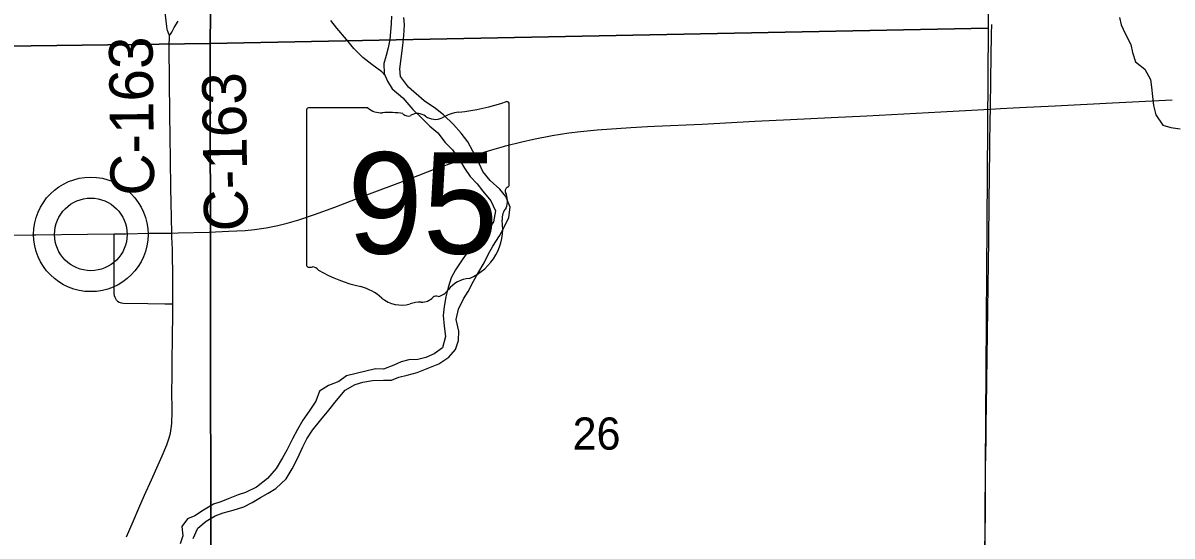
# Model space of a CAD drawing. Extents: x 0 to 45.9, y 0 to 22.
# Drawn here: x 3.224 to 4.718, y 15.053 to 15.719 of the extents above; entities that cross this region are included whole.
import ezdxf

# ---------------------------------------------------------------- set-up
doc = ezdxf.new("R2010")
doc.units = 0
for name, color, linetype in [('GM_X_County_Road', 7, 'Continuous'), ('GM_X_County_Road_Text', 7, 'Continuous'), ('GM_X_Major_River', 7, 'Continuous'), ('GM_X_Minor_River', 7, 'Continuous'), ('GM_X_Section', 7, 'Continuous'), ('GM_X_Section_Text', 7, 'Continuous'), ('GM_X_State_Location', 7, 'Continuous'), ('GM_X_State_Route', 7, 'Continuous'), ('GM_X_State_Shield', 7, 'Continuous'), ('GM_X_Township_Road', 7, 'Continuous'), ('GM_X_Unincorporated', 7, 'Continuous'), ('GM_X_Unincorporated_Location', 7, 'Continuous')]:
    doc.layers.add(name, color=color, linetype=linetype)

msp = doc.modelspace()

# ---------------------------------------------------------------- linework, layer by layer
at = {"layer": 'GM_X_County_Road'}
for points in [[(3.4142, 15.703), (3.4133, 15.7048), (3.4123, 15.7073), (3.4116, 15.7095), (3.4113, 15.7115), (3.4107, 15.7149), (3.4041, 15.7704)], [(3.4171, 15.4464), (3.4162, 15.4859), (3.4161, 15.5045), (3.4157, 15.5418), (3.4148, 15.6008), (3.4139, 15.6878), (3.4142, 15.703)], [(4.475, 15.0359), (4.4752, 15.1016), (4.4753, 15.1451), (4.4755, 15.1544), (4.476, 15.1832), (4.4763, 15.2003), (4.4767, 15.2194), (4.4772, 15.2538), (4.4785, 15.347), (4.4794, 15.4372), (4.48, 15.4869), (4.481, 15.5553), (4.4815, 15.5988), (4.4816, 15.6019), (4.4817, 15.6073)], [(3.4186, 15.3543), (3.4186, 15.3633), (3.4184, 15.3851), (3.418, 15.4255), (3.4173, 15.441), (3.4171, 15.4464)], [(3.3585, 15.0517), (3.367, 15.0716), (3.3743, 15.0887), (3.3818, 15.1058), (3.3907, 15.1256), (3.4047, 15.1568), (3.4106, 15.1712), (3.4138, 15.1801), (3.4155, 15.1861), (3.4166, 15.1923), (3.4172, 15.1986), (3.4177, 15.2142), (3.4174, 15.2422), (3.4177, 15.2577), (3.4177, 15.2701), (3.4178, 15.2856), (3.4182, 15.3043), (3.4181, 15.3167), (3.4187, 15.3353), (3.4187, 15.3478), (3.4186, 15.3543)]]:
    msp.add_lwpolyline(points, dxfattribs=at)
at = {"layer": 'GM_X_Major_River'}
for points in [[(3.4448, 15.0494), (3.451, 15.0626), (3.4618, 15.0719), (3.4736, 15.079), (3.4839, 15.0826), (3.4972, 15.0862), (3.511, 15.0906), (3.5217, 15.0962), (3.5327, 15.1025), (3.5427, 15.1084), (3.5526, 15.1143), (3.5661, 15.127), (3.5739, 15.1398), (3.5805, 15.1534), (3.5875, 15.1685), (3.5926, 15.179), (3.6003, 15.1903), (3.6108, 15.2035), (3.6216, 15.2162), (3.6312, 15.2286), (3.6428, 15.2421), (3.6558, 15.2495), (3.6657, 15.2524), (3.6782, 15.2549), (3.6927, 15.2551), (3.7029, 15.2553), (3.7124, 15.259), (3.7231, 15.2615), (3.7364, 15.2651), (3.7494, 15.2703), (3.7643, 15.2765), (3.7773, 15.2851), (3.7862, 15.2952), (3.7901, 15.3065), (3.7903, 15.3187), (3.7871, 15.3339), (3.7899, 15.3475), (3.7965, 15.3607), (3.8024, 15.3705), (3.8094, 15.3836), (3.8152, 15.3938), (3.8234, 15.4077), (3.8288, 15.4183), (3.8346, 15.4292), (3.8432, 15.4428), (3.849, 15.4529), (3.8553, 15.4665), (3.857, 15.4801), (3.8515, 15.4939), (3.8436, 15.5034), (3.8313, 15.5146), (3.8215, 15.5265), (3.8153, 15.5406), (3.802, 15.5647), (3.7934, 15.5762), (3.7837, 15.5873), (3.7706, 15.6), (3.7601, 15.6081), (3.7454, 15.6182), (3.7251, 15.6359), (3.7147, 15.6497), (3.7137, 15.6596), (3.7154, 15.6732), (3.7175, 15.6899), (3.7188, 15.7032), (3.7198, 15.7168), (3.7188, 15.7263)], [(3.7029, 15.7284), (3.7024, 15.7189), (3.7018, 15.7079), (3.7006, 15.6977), (3.6985, 15.6871), (3.6961, 15.6769), (3.6929, 15.6667), (3.6935, 15.6538), (3.6975, 15.6439), (3.7039, 15.6336), (3.7177, 15.622), (3.7308, 15.607), (3.7409, 15.597), (3.7529, 15.5851), (3.763, 15.5766), (3.7727, 15.564), (3.7821, 15.5544), (3.7921, 15.5402), (3.7977, 15.5306), (3.8051, 15.5199), (3.8141, 15.5103), (3.8216, 15.5007), (3.832, 15.4881), (3.8383, 15.4754), (3.8355, 15.4607), (3.8273, 15.4483), (3.815, 15.4374), (3.8054, 15.4266), (3.7957, 15.413), (3.786, 15.3984), (3.7806, 15.3882), (3.7766, 15.3757), (3.7734, 15.3633), (3.7714, 15.3508), (3.7701, 15.339), (3.7714, 15.3254), (3.7731, 15.3117), (3.7691, 15.2973), (3.7584, 15.2895), (3.7477, 15.2847), (3.737, 15.2822), (3.7253, 15.2816), (3.7154, 15.2791), (3.7058, 15.2746), (3.6925, 15.2695), (3.6819, 15.27), (3.6445, 15.2607)], [(3.6445, 15.2607), (3.6346, 15.2532), (3.6209, 15.2481), (3.6094, 15.2407), (3.6043, 15.2278), (3.5957, 15.2147), (3.5876, 15.203), (3.5806, 15.191), (3.574, 15.1789), (3.567, 15.1642), (3.5611, 15.1541), (3.553, 15.1405), (3.5418, 15.1274), (3.5272, 15.1162), (3.5131, 15.1092), (3.5036, 15.1063), (3.4906, 15.1011), (3.4811, 15.0971), (3.4715, 15.0938), (3.4585, 15.086), (3.4471, 15.079), (3.4375, 15.0749), (3.4302, 15.0648), (3.4315, 15.0526), (3.428, 15.0424)]]:
    msp.add_lwpolyline(points, dxfattribs=at)
at = {"layer": 'GM_X_Minor_River'}
for points in [[(3.6945, 15.6513), (3.6905, 15.6557), (3.6774, 15.6654), (3.6657, 15.6743), (3.6537, 15.6862), (3.6444, 15.6981), (3.6317, 15.7127), (3.6242, 15.7227)], [(4.6495, 15.7263), (4.6517, 15.7168), (4.6568, 15.7057), (4.6642, 15.6912), (4.6664, 15.6809), (4.6704, 15.6687), (4.6824, 15.6595), (4.6898, 15.6457), (4.6912, 15.6358), (4.6925, 15.6237), (4.6939, 15.6123), (4.6968, 15.6001), (4.7057, 15.5867), (4.7163, 15.5835), (4.7284, 15.5818)]]:
    msp.add_lwpolyline(points, dxfattribs=at)
at = {"layer": 'GM_X_Section'}
for points in [[(3.479, 16.7029), (4.4801, 16.7228), (4.4787, 15.7127), (3.467, 15.6926)], [(3.479, 16.7029), (3.467, 15.6926), (2.4689, 15.6797), (2.4763, 16.6833)], [(4.4787, 15.7127), (4.4719, 14.697), (3.9797, 14.6959), (3.4686, 14.6772), (3.467, 15.6926)], [(3.467, 15.6926), (3.4686, 14.6772), (2.4618, 14.6575), (2.4689, 15.6797)]]:
    msp.add_lwpolyline(points, close=True, dxfattribs=at)
at = {"layer": 'GM_X_State_Route'}
for points in [[(4.0359, 15.5847), (4.0449, 15.5852), (4.107, 15.588), (4.1752, 15.5916), (4.2217, 15.5939), (4.2745, 15.5965), (4.321, 15.5989), (4.4171, 15.6041), (4.473, 15.6068), (4.4817, 15.6073), (4.4946, 15.6081), (4.5195, 15.6095), (4.566, 15.6116), (4.6404, 15.6157), (4.718, 15.6193)], [(3.8484, 15.5588), (3.8512, 15.5596), (3.8723, 15.5649), (3.8875, 15.5684), (3.9119, 15.573), (3.9334, 15.5765), (3.9488, 15.5785), (3.9705, 15.5805), (4.0139, 15.5836), (4.0359, 15.5847)], [(3.4171, 15.4464), (3.4257, 15.4465), (3.466, 15.4476), (3.4908, 15.4486), (3.5125, 15.4498), (3.5248, 15.4511), (3.5401, 15.4533), (3.5553, 15.4563), (3.5673, 15.4592), (3.5822, 15.4636), (3.6028, 15.4705), (3.629, 15.48), (3.6639, 15.4932), (3.7278, 15.5173), (3.7597, 15.5296), (3.8095, 15.5472), (3.8302, 15.5538), (3.8484, 15.5588)], [(2.1, 15.4054), (2.1219, 15.4061), (2.1715, 15.4081), (2.214, 15.4101), (2.218, 15.4102), (2.2708, 15.4121), (2.3732, 15.4164), (2.435, 15.419), (2.5044, 15.4217), (2.5827, 15.4248), (2.6511, 15.4278), (2.7096, 15.4297), (2.7146, 15.4298), (2.8637, 15.4346), (2.9102, 15.4358), (2.9816, 15.4382), (3.0499, 15.4401), (3.1307, 15.4419), (3.1835, 15.4434), (3.2362, 15.4441), (3.2403, 15.4442)], [(3.2403, 15.4442), (3.3077, 15.4451), (3.3424, 15.4454), (3.3573, 15.4455), (3.3884, 15.4461), (3.4171, 15.4464)]]:
    msp.add_lwpolyline(points, dxfattribs=at)
at = {"layer": 'GM_X_State_Shield'}
for p, q in [((3.8559, 15.5092), (3.8559, 15.6139)), ((3.5922, 15.6055), (3.5922, 15.4054)), ((3.672, 15.6089), (3.5948, 15.6089)), ((3.8558, 15.5092), (3.8559, 15.5092))]:
    msp.add_line(p, q, dxfattribs=at)
for centre, radius, start, end in [((3.7619, 15.8817), 0.2796, 275.8445, 288.9065), ((3.8529, 15.6143), 0.00294, 351.8621, 97.738), ((3.5952, 15.6059), 0.00305, 98.1301, 188.1301), ((3.6904, 15.6321), 0.0296, 231.6195, 271.1119), ((3.7002, 15.4966), 0.1064, 80.4867, 94.9883), ((3.7244, 15.6069), 0.00855, 219.7921, 297.1024), ((3.7369, 15.5838), 0.0178, 54.4667, 119.1411), ((3.7599, 15.6155), 0.0214, 233.8562, 294.8282), ((3.7976, 15.5478), 0.0563, 97.3462, 120.7689), ((3.8527, 15.5088), 0.00314, 289.6038, 7.7341), ((3.8552, 15.5015), 0.00454, 107.944, 210.337), ((3.8263, 15.4883), 0.0273, 340.033, 23.6496), ((3.8664, 15.4654), 0.0198, 136.8065, 186.9296), ((3.7776, 15.4521), 0.0699, 292.3089, 8.9858), ((3.5953, 15.4049), 0.00308, 171.9584, 258.3066), ((3.5957, 15.4254), 0.0235, 267.339, 280.6039), ((3.6005, 15.3938), 0.00848, 29.7484, 93.2717), ((3.7076, 15.5736), 0.2019, 240.4129, 257.1985), ((3.6474, 15.3154), 0.0632, 47.1842, 75.836), ((3.8071, 15.3492), 0.0383, 94.4031, 142.5768), ((3.7157, 15.3928), 0.0401, 230.7004, 286.2918), ((3.7418, 15.3778), 0.0214, 268.777, 315.5493), ((3.7611, 15.3584), 0.00601, 65.7517, 132.6484), ((3.7586, 15.386), 0.0226, 282.8732, 323.2771), ((3.7389, 15.3236), 0.0329, 85.6951, 111.2099)]:
    msp.add_arc(centre, radius, start, end, dxfattribs=at)
at = {"layer": 'GM_X_Township_Road'}
for points in [[(3.4142, 15.703), (3.4155, 15.7047), (3.4172, 15.7074), (3.4204, 15.7133), (3.4256, 15.7219)], [(4.4817, 15.6073), (4.4824, 15.647), (4.4825, 15.6746), (4.483, 15.7052), (4.4834, 15.7174)], [(3.3452, 15.3593), (3.3443, 15.3609), (3.3435, 15.3626), (3.3428, 15.3646), (3.3423, 15.3677), (3.3421, 15.3709), (3.3423, 15.3835), (3.3423, 15.3962), (3.3423, 15.4183), (3.3422, 15.4342), (3.3423, 15.4405), (3.3424, 15.4454)], [(3.3452, 15.3593), (3.3466, 15.3579), (3.3487, 15.3566), (3.3514, 15.3556), (3.3545, 15.3551), (3.386, 15.3547), (3.4082, 15.3545), (3.4113, 15.3545), (3.4186, 15.3543)]]:
    msp.add_lwpolyline(points, dxfattribs=at)
at = {"layer": 'GM_X_Unincorporated'}
for radius in [0.0744, 0.0472]:
    msp.add_circle((3.3119, 15.4446), radius, dxfattribs=at)
at = {"layer": 'GM_X_Unincorporated_Location'}
msp.add_line((3.3119, 15.4446), (3.3119, 15.4446), dxfattribs=at)

# ---------------------------------------------------------------- texts
at = {"layer": 'GM_X_County_Road_Text'}
for rotation, p in [(90.6423, (3.3945, 15.4951)), (90.8202, (3.5162, 15.4488))]:
    msp.add_text('C-163', height=0.05682, rotation=rotation, dxfattribs=at).set_placement(p)
at = {"layer": 'GM_X_Section_Text'}
msp.add_text('26', height=0.04186, rotation=0, dxfattribs=at).set_placement((3.9384, 15.1648))
at = {"layer": 'GM_X_State_Location'}
for s in ['s', 'r']:
    msp.add_text(s, height=0.000189, dxfattribs=at).set_placement((3.7211, 15.4921))
msp.add_text('95', height=0.000189, rotation=0, dxfattribs=at).set_placement((3.6734, 15.4783))
at = {"layer": 'GM_X_State_Shield'}
msp.add_text('95', height=0.13184, dxfattribs=at).set_placement((3.6455, 15.4195))

doc.saveas('drawing.dxf')
